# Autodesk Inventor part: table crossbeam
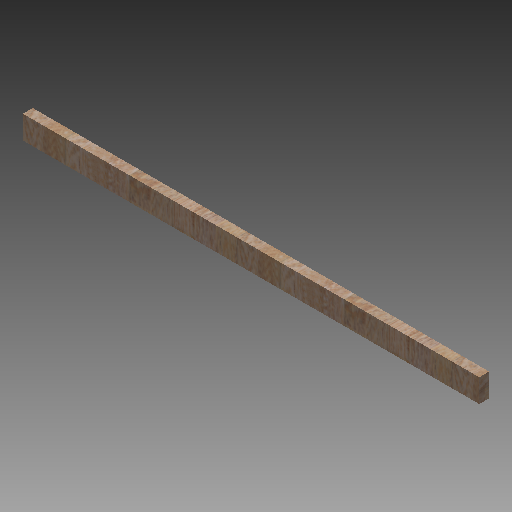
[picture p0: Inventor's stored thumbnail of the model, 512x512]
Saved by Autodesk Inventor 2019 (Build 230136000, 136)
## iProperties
Created: 2013-07
Part Number: table crossbeam
Material: Generic
Document SubType Name: Modeling
Designer: Patrick Rice
Density: 1 g/cm^3
Appearance: Red Oak - Natural
Author: Patrick Rice
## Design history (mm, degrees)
sketch "Sketch1"
  geometry: L1 (44.45, -19.05)-(-44.45, -19.05); L2 (-44.45, -19.05)-(-44.45, 19.05); L3 (-44.45, 19.05)-(44.45, 19.05); L4 (44.45, 19.05)-(44.45, -19.05); L5 (44.45, -19.05)-(-44.45, 19.05); L6 (-44.45, -19.05)-(44.45, 19.05); 1 further point
  constraints: 12 end point, 2 midpoint, 2 parallel, 1 horizontal, 1 perpendicular
  dimensions: "d0" = 88.9 distance of L2.end L3.end; "d1" = 38.1 distance of L1.end L2.end
extrude "Extrusion1" new body sketch "Sketch1" distance "d2" = 1752.6; taper "d3" = 0 deg
body "Solid1"
